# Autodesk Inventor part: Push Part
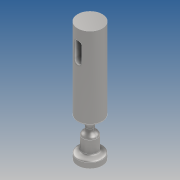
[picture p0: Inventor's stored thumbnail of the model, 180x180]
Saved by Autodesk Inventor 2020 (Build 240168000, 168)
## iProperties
Created: 2019-10
Part Number: Push Part
Material: Generic
Document SubType Name: Modeling
Designer: yello
Density: 1 g/cm^3
Appearance: Default
Author: yello
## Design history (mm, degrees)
sketch "Sketch2" dims "d4" = 3
  geometry: L1 (0, 0)-(2, 0); L2 (0, 0)-(0, -26); L3 (0, -26)-(2.5, -26); L4 (2.5, -26)-(2.5, -24); L5 (2.5, -24)-(3.5, -24); L6 (0, -26)-(0, -28); L7 (0, -28)-(2, -28); L8 (2, -24)-(2, 0); L9 (0, -28)-(0, -32.5); L10 (2, -28)-(2, -30); L11 (0, -32.5)-(2, -32.5); L12 (2, -32.5)-(2, -30); L13 (2, -28)-(2, -27.177); L14 (2, -27.177)-(1, -27.177); L15 (1, -27.177)-(1, -26); L16 (2, -24)-(2, -24.823); L17 (2, -24.823)-(1, -24.823); L18 (1, -24.823)-(1, -26); L19 (2, -31.5)-(2, -34); L20 (3.5, -32.5)-(3.5, -34); L21 (3.5, -34)-(2, -34); L22 (2, -34)-(0, -34); L23 (0, -34)-(0, -32.5); L24 (2, -31.5)-(2, -32.5); L25 (2, -31.5)-(2, -32); L26 (2, -32)-(3.5, -32); L27 (3.5, -32)-(3.5, -32.5); L28 (2, -24)-(2, -23); L29 (2, 0)-(3.5, 0); L30 (3.5, 0)-(3.5, -23.002); L31 (2, -24)-(2, -23.5); L32 (2, -23.5)-(3.5, -23.501); L33 (3.5, -23.501)-(3.5, -23.002)
  constraints: 42 end point, 9 perpendicular, 6 point on line, 6 vertical, 5 horizontal, 3 symmetric about line, 2 midpoint, 1 coincident, 1 horizontal alignment, 14 other
  dimensions: "d0" = 2 distance of L1.start L1.end; "d2" = 26 distance of L1.start L2.end; "d7" = 2 distance of L4.start L4.end; "d8" = 1.5 distance of L5.end L8.start; "d9" = 4.5 distance of L6.end L9.end; "d10" = 2 distance of L7.end L10.end; "d11" = 2.5 distance of L2.end L3.end; "d13" = 2.5 distance of L19.start L19.end; "d15" = 1 distance of L8.start L28.end; "d16" = 1.5 distance of L1.end L29.end; "d25" = 4 distance from line of L10.end L3
revolve "Revolution1" sketch "Sketch2" stored, may be unused: angle "d17" = 90 deg
workplane "Work Plane1"
sketch "Sketch3"
  geometry: L1 (0, 0)-(0, -4); L2 (0, -4)-(0, -8); L3 (-1, -4)-(-1, -8); L4 (1, -8)-(1, -4); C1 r 1 at (0, -4); A1 r 1 centre (0, -4) between (1, -4) and (-1, -4); A2 r 1 centre (0, -8) between (-1, -8) and (1, -8); 3 further points
  constraints: 10 end point, 4 point on circle, 4 tangent, 3 centre point, 2 vertical, 1 coincident, 1 concentric, 1 midpoint, 1 parallel
  dimensions: "d19" = 4 distance of L1.start L1.end; "d20" = 2 diameter of C1; "d26" = 4 distance of L2.start L2.end
extrude "Extrusion2" cut sketch "Sketch3" distance "d27" = 10; taper "d28" = 0 deg
body "Solid1"
other parameters: "d18" = 3.5
